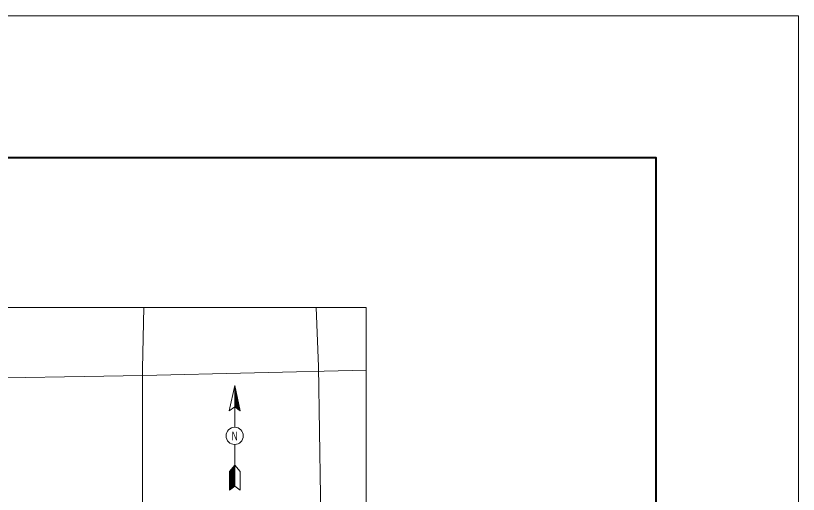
# Model space of a CAD drawing. Extents: x -6.3 to 58.7, y 19.8 to 60.6.
# Drawn here: x 54.076 to 58.676, y 57.769 to 60.58 of the extents above; entities that cross this region are included whole.
import ezdxf

# ---------------------------------------------------------------- set-up
doc = ezdxf.new("R2010")
doc.units = 0
doc.header["$LTSCALE"] = 0.092
for name, color, linetype, lineweight in [('58', 7, 'Continuous', 13), ('60', 7, 'Continuous', 40), ('63', 7, 'Continuous', 13)]:
    doc.layers.add(name, color=color, linetype=linetype, lineweight=lineweight)

msp = doc.modelspace()

# ---------------------------------------------------------------- linework, layer by layer
at = {"layer": '58'}
for p, q in [((55.36297, 58.16326), (55.36297, 58.40743)), ((55.36297, 58.40575), (55.3633, 58.40575)), ((55.36297, 58.40406), (55.36364, 58.40406)), ((55.36297, 58.40205), (55.36431, 58.40205)), ((55.36297, 58.40036), (55.36431, 58.40036)), ((55.36297, 58.39868), (55.36465, 58.39868)), ((55.36297, 58.39734), (55.36532, 58.39734)), ((55.36297, 58.39532), (55.36566, 58.39532)), ((55.36297, 58.39364), (55.36599, 58.39364)), ((55.36297, 58.39196), (55.36633, 58.39196)), ((55.36297, 58.39027), (55.36667, 58.39027)), ((55.36297, 58.38826), (55.367, 58.38826)), ((55.36297, 58.38624), (55.367, 58.38624)), ((55.36297, 58.38489), (55.36801, 58.38489)), ((55.36297, 58.38321), (55.36835, 58.38321)), ((55.36297, 58.38119), (55.36868, 58.38119)), ((55.36297, 58.37985), (55.36902, 58.37985)), ((55.36297, 58.37783), (55.36936, 58.37783)), ((55.36297, 58.37615), (55.36969, 58.37615)), ((55.36297, 58.37413), (55.37003, 58.37413)), ((55.36297, 58.37279), (55.37036, 58.37279)), ((55.36297, 58.37077), (55.37104, 58.37077)), ((55.36297, 58.36909), (55.37104, 58.36909)), ((55.36297, 58.3674), (55.37137, 58.3674)), ((55.36297, 58.36572), (55.37171, 58.36572)), ((55.36297, 58.36371), (55.37238, 58.36371)), ((55.36297, 58.36202), (55.37272, 58.36202)), ((55.36297, 58.36068), (55.37339, 58.36068)), ((55.36297, 58.35866), (55.37339, 58.35866)), ((55.36297, 58.35698), (55.37373, 58.35698)), ((55.36297, 58.3553), (55.37406, 58.3553)), ((55.36297, 58.35328), (55.37474, 58.35328)), ((55.36297, 58.35193), (55.37474, 58.35193)), ((55.36297, 58.34992), (55.37507, 58.34992)), ((55.36297, 58.34823), (55.37575, 58.34823)), ((55.36297, 58.34655), (55.37608, 58.34655)), ((55.36297, 58.34487), (55.37642, 58.34487)), ((55.36297, 58.34319), (55.37675, 58.34319)), ((55.36297, 58.34117), (55.37709, 58.34117)), ((55.36297, 58.33949), (55.37743, 58.33949)), ((55.36297, 58.33781), (55.3781, 58.33781)), ((55.36297, 58.33613), (55.37844, 58.33613)), ((55.36297, 58.33411), (55.37877, 58.33411)), ((55.36297, 58.33243), (55.37877, 58.33243)), ((55.36297, 58.33075), (55.37945, 58.33075)), ((55.36297, 58.32906), (55.37978, 58.32906)), ((55.36297, 58.32772), (55.38045, 58.32772)), ((55.36297, 58.3257), (55.38045, 58.3257)), ((55.36297, 58.32368), (55.38113, 58.32368)), ((55.36297, 58.322), (55.38113, 58.322)), ((55.36297, 58.32032), (55.3818, 58.32032)), ((55.36297, 58.31864), (55.38214, 58.31864)), ((55.36297, 58.31662), (55.38214, 58.31662)), ((55.36297, 58.31527), (55.38281, 58.31527)), ((55.36297, 58.31359), (55.38315, 58.31359)), ((55.36297, 58.31157), (55.38348, 58.31157)), ((55.36297, 58.30989), (55.38382, 58.30989)), ((55.36297, 58.30821), (55.38449, 58.30821)), ((55.36297, 58.30619), (55.38449, 58.30619)), ((55.36297, 58.30451), (55.38516, 58.30451)), ((55.36297, 58.30317), (55.38516, 58.30317)), ((55.36297, 58.30115), (55.38584, 58.30115)), ((55.36297, 58.29947), (55.38584, 58.29947)), ((55.36297, 58.29779), (55.38651, 58.29779)), ((55.36297, 58.2961), (55.38684, 58.2961)), ((55.36297, 58.29409), (55.38718, 58.29409)), ((55.36297, 58.2924), (55.38752, 58.2924)), ((55.36297, 58.29072), (55.38785, 58.29072)), ((55.36297, 58.28904), (55.38819, 58.28904)), ((55.36297, 58.28736), (55.38886, 58.28736)), ((55.36297, 58.28568), (55.3892, 58.28568)), ((55.36297, 58.28366), (55.38954, 58.28366)), ((55.36465, 58.28198), (55.38987, 58.28198)), ((55.367, 58.2803), (55.39021, 58.2803)), ((55.36936, 58.27861), (55.39054, 58.27861)), ((55.37137, 58.2766), (55.39054, 58.2766)), ((55.37373, 58.27492), (55.39122, 58.27492)), ((55.37608, 58.27323), (55.39155, 58.27323)), ((55.3781, 58.27155), (55.39223, 58.27155)), ((55.38045, 58.26987), (55.39256, 58.26987)), ((55.38247, 58.26819), (55.3929, 58.26819)), ((55.38516, 58.26651), (55.39323, 58.26651)), ((55.38684, 58.26449), (55.39357, 58.26449)), ((55.3892, 58.26281), (55.39391, 58.26281)), ((55.39122, 58.26113), (55.39458, 58.26113)), ((55.39357, 58.25911), (55.39492, 58.25911)), ((55.36297, 57.81751), (55.36297, 58.06169)), ((55.34312, 57.9174), (55.36297, 57.9174)), ((55.3448, 57.91875), (55.36297, 57.91875)), ((55.34581, 57.92077), (55.36297, 57.92077)), ((55.34749, 57.92278), (55.36297, 57.92278)), ((55.34884, 57.92413), (55.36297, 57.92413)), ((55.35052, 57.92581), (55.36297, 57.92581)), ((55.35187, 57.92783), (55.36297, 57.92783)), ((55.35355, 57.92951), (55.36297, 57.92951)), ((55.35489, 57.93119), (55.36297, 57.93119)), ((55.35624, 57.93287), (55.36297, 57.93287)), ((55.35758, 57.93456), (55.36297, 57.93456)), ((55.35927, 57.93624), (55.36297, 57.93624)), ((55.36061, 57.93825), (55.36297, 57.93825)), ((55.36196, 57.93994), (55.36297, 57.93994)), ((55.33169, 57.90328), (55.36297, 57.90328)), ((55.33169, 57.90126), (55.36297, 57.90126)), ((55.33169, 57.89991), (55.36297, 57.89991)), ((55.33169, 57.89823), (55.36297, 57.89823)), ((55.33169, 57.89621), (55.36297, 57.89621)), ((55.33169, 57.89453), (55.36297, 57.89453)), ((55.33169, 57.89285), (55.36297, 57.89285)), ((55.33169, 57.89117), (55.36297, 57.89117)), ((55.33169, 57.88949), (55.36297, 57.88949)), ((55.33169, 57.88781), (55.36297, 57.88781)), ((55.33169, 57.88579), (55.36297, 57.88579)), ((55.33169, 57.88411), (55.36297, 57.88411)), ((55.33169, 57.88242), (55.36297, 57.88242)), ((55.33169, 57.88074), (55.36297, 57.88074)), ((55.33169, 57.87873), (55.36297, 57.87873)), ((55.33169, 57.87704), (55.36297, 57.87704)), ((55.33169, 57.8757), (55.36297, 57.8757)), ((55.33169, 57.87368), (55.36297, 57.87368)), ((55.33169, 57.87166), (55.36297, 57.87166)), ((55.33169, 57.87032), (55.36297, 57.87032)), ((55.33303, 57.90496), (55.36297, 57.90496)), ((55.33471, 57.90664), (55.36297, 57.90664)), ((55.33606, 57.90866), (55.36297, 57.90866)), ((55.33741, 57.91034), (55.36297, 57.91034)), ((55.33875, 57.91202), (55.36297, 57.91202)), ((55.34043, 57.9137), (55.36297, 57.9137)), ((55.34178, 57.91538), (55.36297, 57.91538)), ((55.33169, 57.8683), (55.36297, 57.8683)), ((55.33169, 57.86662), (55.36297, 57.86662)), ((55.33169, 57.8646), (55.36297, 57.8646)), ((55.33169, 57.86325), (55.36297, 57.86325)), ((55.33169, 57.86157), (55.36297, 57.86157)), ((55.33169, 57.85989), (55.36297, 57.85989)), ((55.33169, 57.85821), (55.36297, 57.85821)), ((55.33169, 57.85619), (55.36297, 57.85619)), ((55.33169, 57.85451), (55.36297, 57.85451)), ((55.33169, 57.85283), (55.36297, 57.85283)), ((55.33169, 57.85115), (55.36297, 57.85115)), ((55.33169, 57.84913), (55.36297, 57.84913)), ((55.33169, 57.84778), (55.36297, 57.84778)), ((55.33169, 57.84577), (55.36297, 57.84577)), ((55.33169, 57.84408), (55.36297, 57.84408)), ((55.33169, 57.8424), (55.36297, 57.8424)), ((55.33169, 57.84072), (55.36297, 57.84072)), ((55.33169, 57.8387), (55.36297, 57.8387)), ((55.33169, 57.83702), (55.36297, 57.83702)), ((55.33169, 57.83534), (55.36297, 57.83534)), ((55.33169, 57.83366), (55.36297, 57.83366)), ((55.33169, 57.83164), (55.36297, 57.83164)), ((55.33169, 57.82996), (55.36297, 57.82996)), ((55.33169, 57.82861), (55.36297, 57.82861)), ((55.33169, 57.82659), (55.36297, 57.82659)), ((55.33169, 57.82458), (55.36297, 57.82458)), ((55.33169, 57.8229), (55.36297, 57.8229)), ((55.33169, 57.82121), (55.36297, 57.82121)), ((55.33169, 57.81987), (55.36297, 57.81987)), ((55.33169, 57.81819), (55.36297, 57.81819)), ((55.33169, 57.81617), (55.36229, 57.81617)), ((55.33169, 57.81449), (55.35994, 57.81449)), ((55.33169, 57.81281), (55.35758, 57.81281)), ((55.33169, 57.81112), (55.35523, 57.81112)), ((55.33169, 57.80911), (55.35288, 57.80911)), ((55.33169, 57.80709), (55.35052, 57.80709)), ((55.33169, 57.80574), (55.34884, 57.80574)), ((55.33169, 57.80406), (55.34615, 57.80406)), ((55.33169, 57.80204), (55.34413, 57.80204)), ((55.33169, 57.80036), (55.34178, 57.80036)), ((55.33169, 57.79868), (55.33942, 57.79868)), ((55.33169, 57.797), (55.33741, 57.797)), ((55.33169, 57.79498), (55.33471, 57.79498)), ((55.33169, 57.79364), (55.3327, 57.79364))]:
    msp.add_line(p, q, dxfattribs=at)
for points in [[(48.79238, 58.86555), (56.13506, 58.86555), (56.13506, 51.30268), (48.79238, 51.30268)], [(55.36297, 58.40743), (55.33101, 58.25844), (55.36297, 58.28366)], [(55.36297, 58.40743), (55.39492, 58.25844), (55.36297, 58.28366)], [(55.36297, 57.94128), (55.33169, 57.90328), (55.33169, 57.79263), (55.36297, 57.81718)], [(55.36297, 57.94128), (55.39492, 57.90328), (55.39458, 57.79296), (55.36297, 57.81751)]]:
    msp.add_lwpolyline(points, close=True, dxfattribs=at)
for points in [[(52.55288, 51.30268), (56.13506, 51.30268), (56.13506, 58.86555), (51.92068, 58.86555)], [(54.82902, 58.86555), (54.82193, 58.50887), (54.82193, 57.75509), (54.83195, 56.96955), (54.81691, 56.22078), (54.79184, 55.43022), (54.76176, 54.73494), (54.71162, 53.96945), (54.65312, 53.22904), (54.58794, 52.44016), (54.43457, 51.30268)], [(55.84201, 58.86555), (55.8565, 58.5189), (55.86653, 57.7601), (55.85148, 56.98459), (55.83644, 56.20574), (55.80134, 55.40682), (55.77627, 54.64636), (55.73282, 53.87586), (55.64758, 53.11539), (55.38128, 51.30268)], [(48.79238, 58.47873), (50.219, 58.4604), (51.35218, 58.44536), (52.51378, 58.4721), (53.67036, 58.44703), (54.8236, 58.46709), (56.13506, 58.49831)]]:
    msp.add_lwpolyline(points, dxfattribs=at)
msp.add_circle((55.36307, 58.11239), 0.05059, dxfattribs=at)
at = {"layer": '60'}
msp.add_lwpolyline([(-3.73781, 29.96257), (-3.73781, 20.65308), (57.84015, 20.65308), (57.84016, 59.74412), (-3.73781, 59.74412), (-3.73781, 40.1986), (-3.73781, 40.1986)], dxfattribs=at)
at = {"layer": '63'}
msp.add_lwpolyline([(-6.28685, 19.8174), (58.67584, 19.8174), (58.67584, 60.5798), (-6.28685, 60.5798)], close=True, dxfattribs=at)

# ---------------------------------------------------------------- texts
at = {"layer": '58', "width": 0.7}
msp.add_text('N', height=0.05228, dxfattribs=at).set_placement((55.34548, 58.08557))

doc.saveas('drawing.dxf')
